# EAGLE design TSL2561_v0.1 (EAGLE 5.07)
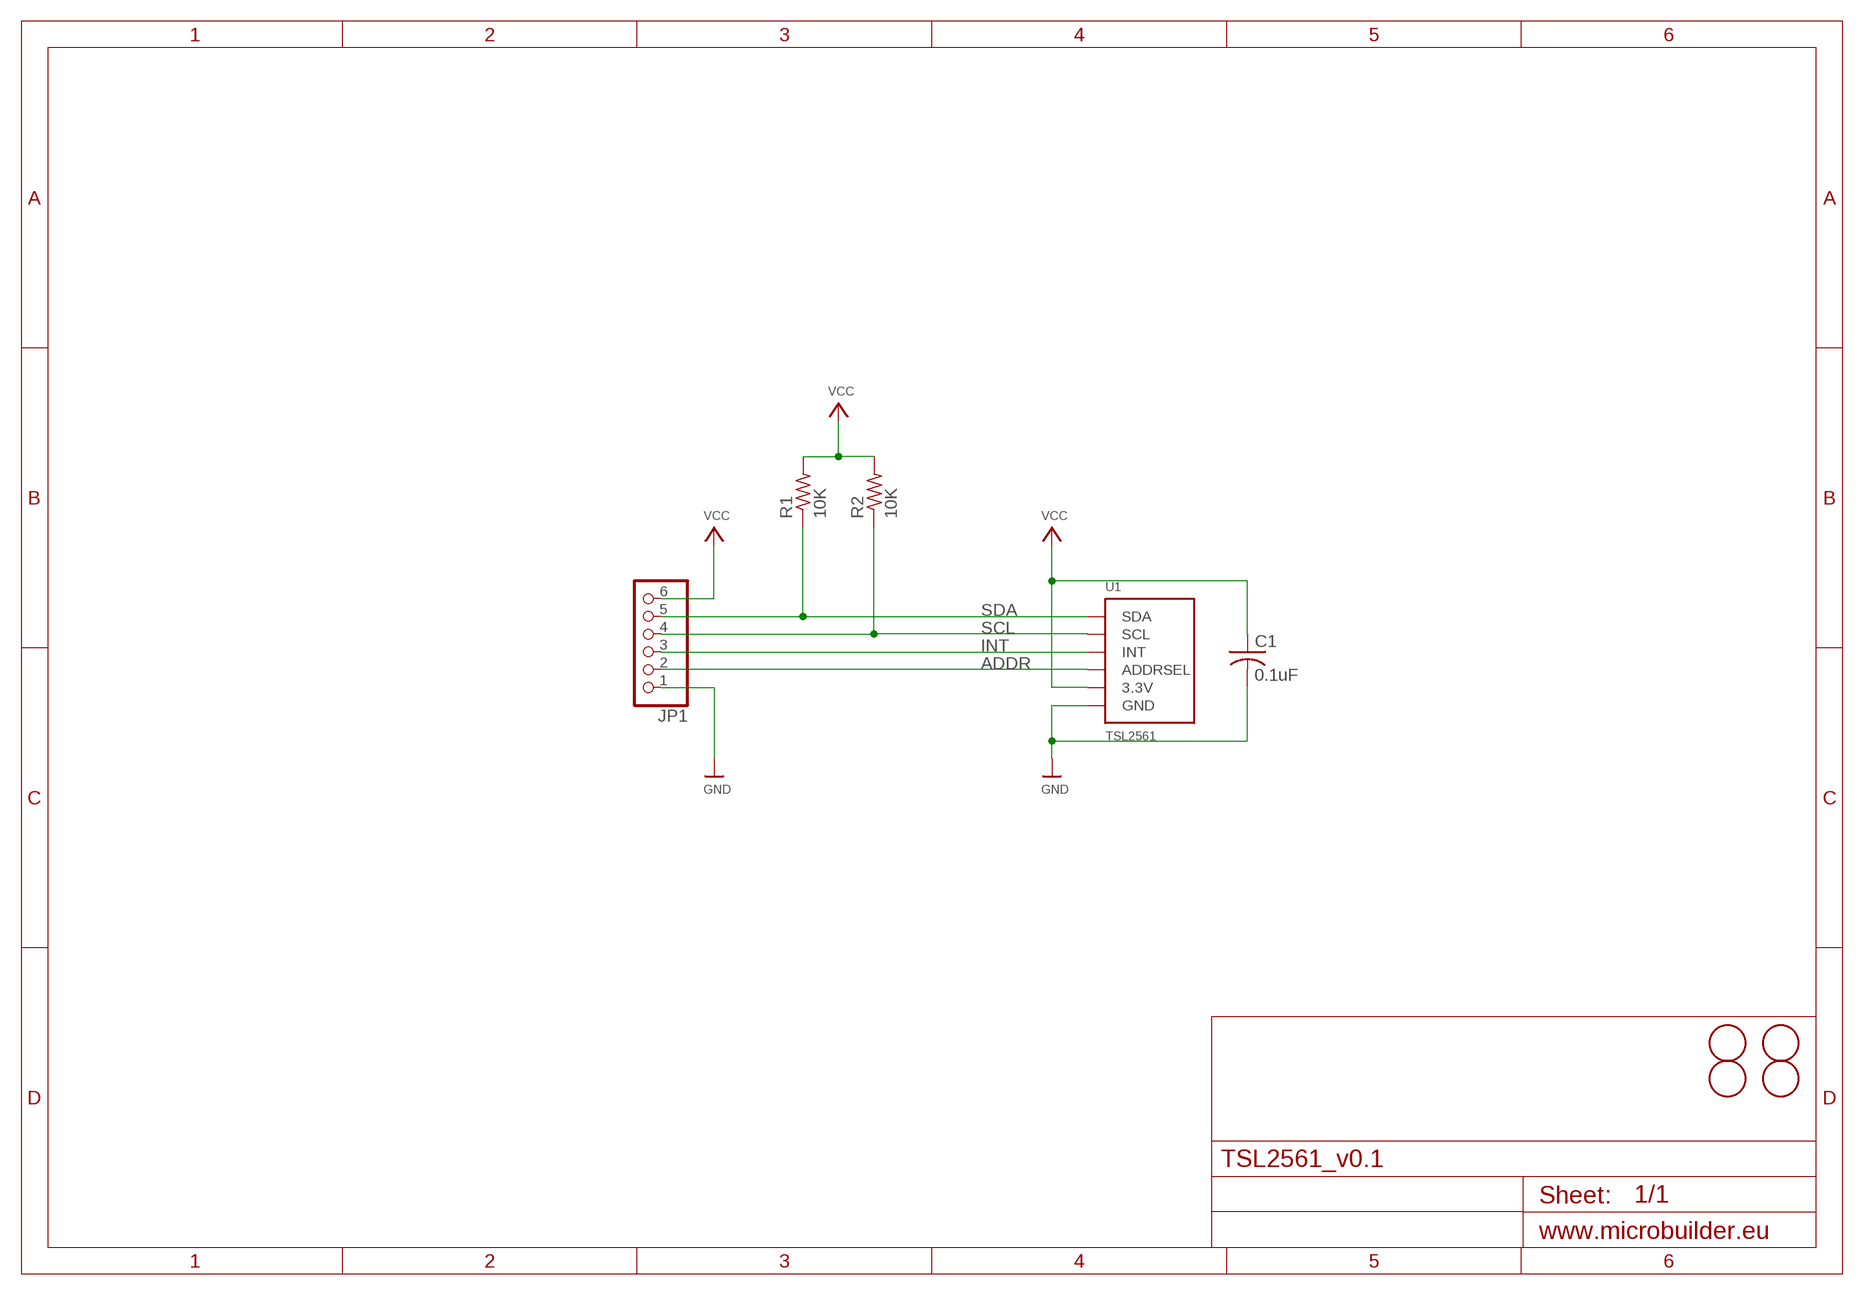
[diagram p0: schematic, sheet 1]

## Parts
C1  0.1uF  C-USC0805  [C0805]
JP1  HEADER-1X676MIL  [1X06_ROUND_76]
R1  10K  R-US_R0805  [R0805]
R2  10K  R-US_R0805  [R0805]
U1  TSL2561  [TSL2561_FN]
U$2  FIDUCIAL  [FIDUCIAL_1MM]
U$4  FIDUCIAL  [FIDUCIAL_1MM]
U$5  MOUNTINGHOLE2.0  [MOUNTINGHOLE_2.0_PLATED]
U$6  MOUNTINGHOLE2.0  [MOUNTINGHOLE_2.0_PLATED]

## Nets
ADDR: JP1.2 U1.ADR(ADDRSEL)
GND: C1.2 JP1.1 U1.VSS(GND)
INT: JP1.3 U1.INT
SCL: JP1.4 R2.1 U1.CLK(SCL)
SDA: JP1.5 R1.1 U1.DATA(SDA)
VCC: C1.1 JP1.6 R1.2 R2.2 U1.VDD(3.3V)

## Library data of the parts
C1 = adafruit:C-US: CAPACITOR, American symbol
JP1 = microbuilder:HEADER-1X6: PIN HEADER
R1 R2 = adafruit:R-US_: RESISTOR, American symbol
U1 = microbuilder:TSL2561: TSL2561 Light-To-Digital Sensor Mouser Part Numbers: CS (obsolete): 856-TSL2561CS DFN (cheapest): 856-TSL2561FN
U$2 U$4 = adafruit:FIDUCIAL: For use by pick and place machines to calibrate the vision/machine, 1mm
U$5 U$6 = microbuilder:MOUNTINGHOLE: Mounting Hole

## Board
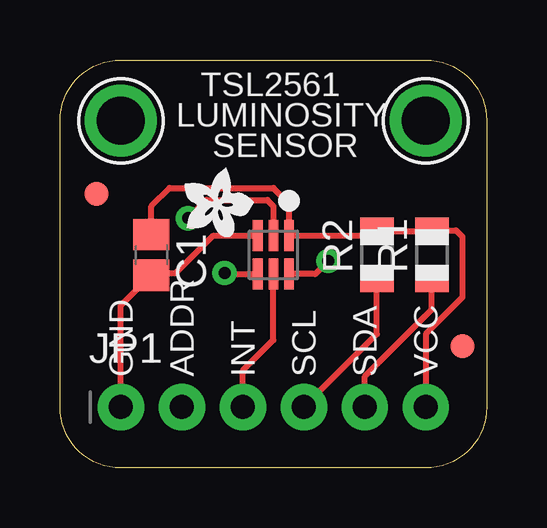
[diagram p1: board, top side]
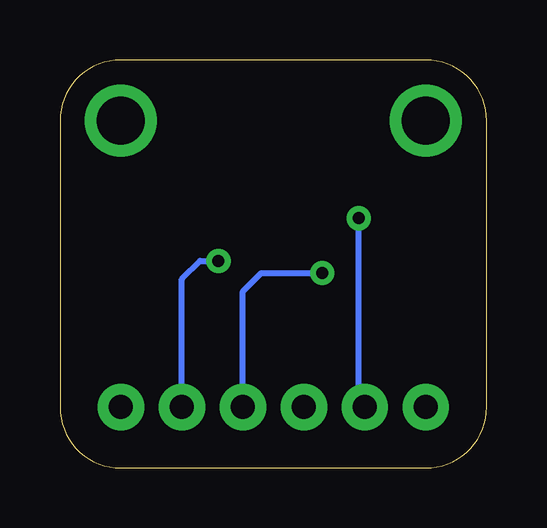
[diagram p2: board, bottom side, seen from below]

Size 17.78 x 17.02 mm. Coordinates in mm from the lower left corner, seen from the top.
Outline: 0,2.54 0,14.48 arc-90 2.54,17.02 15.24,17.02 arc-90 17.78,14.48 17.78,2.54 arc-90 15.24,0 2.54,0 arc-90 0,2.54
Copper layers (1*16): Top 0.035mm / dielectric 1.5mm / Bottom 0.035mm
Design rules "default *": minimum track width 8mil, minimum drill 0.4mm, track to track 8mil, track to pad 8mil, pad to pad 8mil, via to via 8mil, smd to smd 8mil, copper to edge 20mil, drill to drill 8mil, minimum pad ring 8mil, minimum via ring 10mil, stop-mask expansion 3mil, vias tented up to drill 20mil, thermal gap 8mil

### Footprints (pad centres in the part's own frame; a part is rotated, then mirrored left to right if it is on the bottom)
C0805 = smd 1.3 x 1.5: 1 -0.85,0; 2 0.85,0
1X06_ROUND_76 = drill 1 pad 1.93 round: 1 -6.35,0; 2 -3.81,0; 3 -1.27,0; 4 1.27,0; 5 3.81,0; 6 6.35,0
R0805 = smd 1.1 x 1.4: 1 -1,0; 2 1,0
TSL2561_FN = smd 1.3 x 0.4: ADR -0.8,0; CLK 0.8,-0.65; DATA 0.8,0.65; INT 0.8,0; VDD -0.8,0.65; VSS -0.8,-0.65
FIDUCIAL_1MM = smd 1 x 1: 1 0,0
MOUNTINGHOLE_2.0_PLATED = drill 2 pad 3 round: P$1 0,0

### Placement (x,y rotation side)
C1  3.81,8.89 270 top
JP1  8.89,2.54 0 top
R1  15.49,8.89 90 top
R2  13.21,8.89 90 top
U1  8.89,8.89 270 top
U$2  1.52,11.43 0 top
U$4  16.76,5.08 0 top
U$5  15.24,14.48 0 top
U$6  2.54,14.48 0 top
U$7  [ADAFRUIT200MIL]  6.6,11.18 270 top

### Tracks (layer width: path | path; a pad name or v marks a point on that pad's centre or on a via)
ADDR  (via drill 0.5)
  Top 0.254: U1.ADR 8.89,10.92 8.64,11.18 6.1,11.18 v5.33,10.41
  Bottom 0.254: v5.33,10.41 5.33,2.79 JP1.2
GND
  Top 0.254: JP1.1 2.54,6.77 C1.2 3.9,8.13 4.83,8.13 6.39,9.69 U1.VSS
INT
  Top 0.254: U1.INT 8.89,5.33 7.62,4.06 JP1.3
SCL  (via drill 0.5)
  Top 0.254: JP1.4 13.21,5.59 R2.1 | U1.CLK 6.9,8.09 v6.86,8.13
  Bottom 0.254: v6.86,8.13 9.4,8.13 10.16,7.37 JP1.4
SDA  (via drill 0.5)
  Top 0.254: R1.1 15.49,6.6 12.7,3.81 JP1.5 | U1.DATA 10.63,8.09 v11.18,8.64
  Bottom 0.254: v11.18,8.64 11.94,8.64 12.7,7.87 JP1.5
VCC
  Top 0.254: C1.1 3.81,10.92 4.57,11.68 8.89,11.68 9.54,11.03 U1.VDD 13.01,9.69 R2.2 R1.2 15.51,9.91 16.51,9.91 16.76,9.65 16.76,7.11 15.24,5.59 JP1.6

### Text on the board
tPlace: TSL2561 | LUMINOSITY | SENSOR | GND | ADDR | INT | SCL | SDA | VCC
